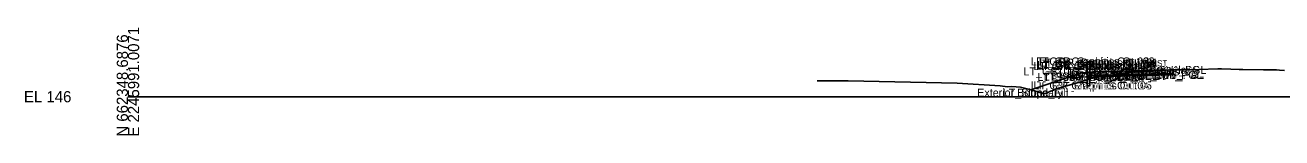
# Model space of a CAD drawing. Extents: x -26 to 603, y -10 to 9526.
# Drawn here: x -25.7 to 288.4, y 2990.3 to 3017.3 of the extents above; entities that cross this region are included whole.
import ezdxf

# ---------------------------------------------------------------- set-up
doc = ezdxf.new("R2010")
doc.units = 0
for name, color, linetype in [('Default', 7, 'Continuous'), ('Exist Cross Section Cell', 7, 'Continuous'), ('Exist XS Ground Line', 7, 'Continuous'), ('Prop CMT Guardrail Graphics', 7, 'Continuous'), ('Prop CMT Pvmt Course 1', 7, 'Continuous'), ('Prop CMT Pvmt Course 2', 7, 'Continuous'), ('Prop CMT Pvmt Course 3', 7, 'Continuous'), ('Prop CMT Pvmt Surface', 7, 'Continuous'), ('Prop CMT Pvmt Surface Shoulder', 7, 'Continuous'), ('Prop CMT Shld Paved Course 1', 7, 'Continuous'), ('Prop CMT Shld Paved Course 2', 7, 'Continuous'), ('Prop CMT Shld Paved Course 3', 7, 'Continuous'), ('Prop CMT Slope Grass', 7, 'Continuous'), ('Prop CMT Subgrade Earthwork', 7, 'Continuous'), ('Prop XS SE Text', 7, 'Continuous'), ('Prop XS Side Slope Text', 7, 'Continuous'), ('Scratch_Level_2', 7, 'Continuous')]:
    doc.layers.add(name, color=color, linetype=linetype)

msp = doc.modelspace()

# ---------------------------------------------------------------- linework, layer by layer
at = {"layer": 'Exist Cross Section Cell'}
msp.add_line((0, 3000), (300, 3000), dxfattribs=at)
at = {"layer": 'Exist XS Ground Line'}
for p, q in [((240.69, 3004.53), (251.23, 3006.28)), ((251.23, 3006.28), (251.75, 3006.18)), ((251.75, 3006.18), (252.66, 3006.25)), ((252.66, 3006.25), (256.25, 3006.42)), ((256.25, 3006.42), (256.67, 3006.47)), ((256.67, 3006.47), (257.94, 3006.52)), ((257.94, 3006.52), (258.42, 3006.54)), ((258.42, 3006.54), (258.97, 3006.66)), ((258.97, 3006.66), (259.49, 3006.67)), ((259.49, 3006.67), (260.33, 3006.69)), ((260.33, 3006.69), (260.72, 3006.7)), ((260.72, 3006.7), (261.25, 3006.7)), ((261.25, 3006.7), (261.79, 3006.71)), ((261.79, 3006.71), (262.59, 3006.73)), ((262.59, 3006.73), (263.53, 3006.75)), ((263.53, 3006.75), (267.65, 3006.81)), ((267.65, 3006.81), (272.37, 3006.94)), ((272.37, 3006.94), (273.35, 3006.97)), ((273.35, 3006.97), (275.62, 3006.87)), ((275.62, 3006.87), (277.69, 3006.85)), ((277.69, 3006.85), (278.63, 3006.83)), ((278.63, 3006.83), (283.81, 3006.73)), ((283.81, 3006.73), (284.36, 3006.71)), ((284.36, 3006.71), (285.25, 3006.72)), ((285.25, 3006.72), (287.03, 3006.69)), ((287.03, 3006.69), (287.78, 3006.65)), ((287.78, 3006.65), (289.02, 3006.53)), ((172.23, 3003.96), (179.98, 3003.93)), ((179.98, 3003.93), (207.25, 3003.39)), ((207.25, 3003.39), (218.01, 3002.69)), ((232.59, 3002.16), (238.19, 3003.76)), ((238.19, 3003.76), (240.69, 3004.53)), ((218.01, 3002.69), (219.83, 3002.44)), ((219.83, 3002.44), (220.87, 3002.57)), ((220.87, 3002.57), (223.04, 3002.42)), ((223.04, 3002.42), (225.41, 3001.83)), ((225.41, 3001.83), (229.08, 3000.72)), ((229.08, 3000.72), (231.47, 3001.68)), ((231.47, 3001.68), (232.59, 3002.16))]:
    msp.add_line(p, q, dxfattribs=at)
at = {"layer": 'Prop CMT Guardrail Graphics'}
for points in [[(239.73, 3002.71), (239.73, 3008.71)], [(239.73, 3008.71), (241.07, 3008.71), (241.34, 3008.41)], [(241.34, 3007.83), (241.07, 3007.54), (240.4, 3007.54)], [(240.4, 3007.54), (240.4, 3002.71)], [(241.34, 3008.41), (241.07, 3008.12)], [(241.07, 3008.12), (241.34, 3007.83)], [(240.4, 3002.71), (239.73, 3002.71)]]:
    msp.add_lwpolyline(points, dxfattribs=at)
at = {"layer": 'Prop CMT Pvmt Course 1'}
for points in [[(261.25, 3006.7), (251.1, 3006.45)], [(251.1, 3006.45), (251.1, 3005.53)], [(261.25, 3005.79), (261.25, 3006.7)], [(251.1, 3005.53), (261.25, 3005.79)]]:
    msp.add_lwpolyline(points, dxfattribs=at)
at = {"layer": 'Prop CMT Pvmt Course 2'}
for points in [[(261.25, 3005.79), (251.1, 3005.53)], [(251.1, 3005.53), (251.1, 3005.2)], [(251.1, 3005.2), (261.25, 3005.45)], [(261.25, 3005.45), (261.25, 3005.79)]]:
    msp.add_lwpolyline(points, dxfattribs=at)
at = {"layer": 'Prop CMT Pvmt Course 3'}
for points in [[(261.25, 3005.45), (251.1, 3005.2)], [(251.1, 3005.2), (261.25, 3005.45)], [(251.1, 3005.2), (251.1, 3005.2)], [(261.25, 3005.45), (261.25, 3005.45)]]:
    msp.add_lwpolyline(points, dxfattribs=at)
at = {"layer": 'Prop CMT Pvmt Surface'}
msp.add_lwpolyline([(261.25, 3006.7), (251.1, 3006.45)], dxfattribs=at)
at = {"layer": 'Prop CMT Pvmt Surface Shoulder'}
msp.add_lwpolyline([(251.1, 3006.45), (241.34, 3006.21)], dxfattribs=at)
at = {"layer": 'Prop CMT Shld Paved Course 1'}
for p, q in [((241.34, 3006.21), (240.4, 3005.27)), ((251.1, 3006.45), (246.45, 3006.33))]:
    msp.add_line(p, q, dxfattribs=at)
for points in [[(251.1, 3005.53), (251.1, 3006.45)], [(245.51, 3005.39), (251.1, 3005.53)]]:
    msp.add_lwpolyline(points, dxfattribs=at)
at = {"layer": 'Prop CMT Shld Paved Course 2'}
for p, q in [((240.4, 3005.27), (240.06, 3004.92)), ((251.1, 3005.53), (240.4, 3005.27))]:
    msp.add_line(p, q, dxfattribs=at)
for points in [[(245.17, 3005.05), (251.1, 3005.2)], [(251.1, 3005.2), (251.1, 3005.53)]]:
    msp.add_lwpolyline(points, dxfattribs=at)
at = {"layer": 'Prop CMT Shld Paved Course 3'}
for points in [[(251.1, 3005.2), (245.17, 3005.05), (244.67, 3005.04)], [(244.67, 3005.04), (251.1, 3005.2)], [(244.67, 3005.04), (244.67, 3005.04)], [(251.1, 3005.2), (251.1, 3005.2)]]:
    msp.add_lwpolyline(points, dxfattribs=at)
at = {"layer": 'Prop CMT Slope Grass'}
for points in [[(238.34, 3005.97), (225.68, 3001.75)], [(241.34, 3006.21), (238.34, 3005.97)]]:
    msp.add_lwpolyline(points, dxfattribs=at)
at = {"layer": 'Prop CMT Subgrade Earthwork'}
for points in [[(244.67, 3005.04), (234.82, 3004.79)], [(251.1, 3005.2), (244.67, 3005.04)], [(261.25, 3005.45), (251.1, 3005.2)]]:
    msp.add_lwpolyline(points, dxfattribs=at)

# ---------------------------------------------------------------- texts
at = {"layer": 'Default'}
msp.add_text('-', height=0.0001, dxfattribs=at).set_placement((0, 3000))
msp.add_text('-', height=0.0001, dxfattribs=at).set_placement((0, 3000))
msp.add_text('-', height=0.0001, dxfattribs=at).set_placement((0, 3000))
msp.add_text('-', height=0.0001, dxfattribs=at).set_placement((0, 3000))
at = {"layer": 'Exist Cross Section Cell'}
for s, p in [('N 662348.6876', (0, 2990)), ('E 2245991.0071', (2.8, 2990))]:
    msp.add_text(s, height=2.8, rotation=90, dxfattribs=at).set_placement(p)
msp.add_text('EL 146', height=2.8, dxfattribs=at).set_placement((-26, 2998.6))
at = {"layer": 'Prop XS SE Text'}
msp.add_text('EXIST', height=1.5, rotation=1.4321, dxfattribs=at).set_placement((254, 3007.52))
at = {"layer": 'Prop XS Side Slope Text'}
msp.add_text('3:1', height=1.5, rotation=18.4332, dxfattribs=at).set_placement((231.22, 3004.3))
at = {"layer": 'Scratch_Level_2'}
for s, p in [('LT_GR_Graphics Out 03', (225.67, 3007.83)), ('LT_GR_Graphics Out 02', (227, 3007.83)), ('LT_GR_Graphics Out 09', (227, 3007.24)), ('LT_GR_Graphics Out 08', (227.27, 3006.95)), ('LT_GR_Graphics Out 01', (227.84, 3007.54)), ('LT_GS_OS_GR_Face_Graphics', (223.83, 3005.33)), ('LT_GR_Graphics Out 06', (226.29, 3006.66)), ('LT_GR_Graphics Out 07', (227, 3006.66)), ('LT_Sub_OSS_DLT', (227.28, 3003.92)), ('LT_Sub_Trench_Out', (228.88, 3004.04)), ('LT_PS3_Shelf_Out', (230.66, 3004.04)), ('LT_GS_OS_CTL', (232.75, 3005.09)), ('LT_PS3_OEOP', (235.41, 3004.05)), ('LT_PS2_OEOP', (235.75, 3004.39)), ('LT_PS1_OEOP', (237.26, 3005.33)), ('LT_Sub_OEOT', (241.18, 3004.2)), ('LT_PV2_OEOT', (241.27, 3004.53)), ('LT_PV3_OEOT', (241.27, 3004.2)), ('LT_PV1_OEOT', (241.84, 3005.45)), ('Exterior Boundary', (245.39, 3005.7)), ('LT_Sub_PGL', (252.36, 3004.45)), ('LT_PV2_PGL', (252.46, 3004.79)), ('LT_PV3_PGL', (252.46, 3004.45)), ('LT_PV1_PGL', (253.03, 3005.7)), ('LT_GR_Graphics Out 04', (225.67, 3001.83)), ('LT_GR_Graphics Out 05', (226.34, 3001.83)), ('Exterior Boundary', (212.27, 3000.01)), ('Exterior Boundary', (212.27, 3000.01)), ('LT_Slope_Fill', (218.65, 3000.01)), ('LT_Slope_Fill', (218.65, 3000.01))]:
    msp.add_text(s, height=2, dxfattribs=at).set_placement(p)

doc.saveas('drawing.dxf')
